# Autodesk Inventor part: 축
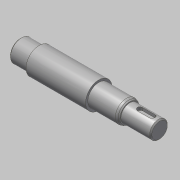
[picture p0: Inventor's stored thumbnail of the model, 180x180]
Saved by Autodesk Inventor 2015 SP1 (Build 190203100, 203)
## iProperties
Created: 2016-06
Part Number: 축
Material: 강철, 연강
Document SubType Name: Modeling
Designer: mduedu
Density: 7.86 g/cm^3
Appearance: 강철
Author: mduedu
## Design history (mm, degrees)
sketch "스케치1"
  geometry: L1 (-63, 0)-(63, 0); L2 (-63, 0)-(-63, 10); L3 (-63, 10)-(-46, 10); L4 (-46, 10)-(-46, 12); L5 (-46, 12)-(8, 12); L6 (8, 12)-(8, 10); L7 (8, 10)-(36, 10); L8 (36, 10)-(36, 8); L9 (36, 8)-(63, 8); L10 (63, 8)-(63, 0); 2 further points
  constraints: 20 end point, 5 parallel, 2 perpendicular, 1 coincident, 1 collinear, 1 horizontal, 1 midpoint, 1 vertical
  dimensions: "d0" = 126 distance of L1.start L1.end; "d2" = 16 diameter of L9 L1; "d3" = 20 diameter of L7 L1; "d4" = 24 diameter of L5 L1; "d5" = 20 diameter of L3 L1; "d6" = 17 distance of L2.end L3.end; "d7" = 27 distance of L8.end L9.end; "d8" = 55 distance from line of L5.end L10
revolve "회전1" sketch "스케치1" stored, may be unused: angle "d9" = 90 deg
chamfer "모따기1" distance "d10" = 2; stored, may be unused: second distance "d11" = 2, angle "d12" = 30 deg
fillet "모깎기1" dims "d13" = 4
node "작업 평면1"
sketch "스케치2"
  geometry: L1 (-4, 2.5)-(7, 2.5); L2 (7, -2.5)-(-4, -2.5); L3 (-4, 0)-(7, 0); L4 (-13.5, 8.845)-(-13.5, -8.845) reference; A1 r 2.5 centre (-4, 0) between (-4, 2.5) and (-4, -2.5); A2 r 2.5 centre (7, 0) between (7, -2.5) and (7, 2.5); 1 further point
  constraints: 6 end point, 4 point on circle, 3 tangent, 2 centre point, 2 parallel, 1 horizontal, 1 horizontal alignment
  dimensions: "d14" = 7 distance edge to line of A1 L4; "d15" = 5 distance between parallel lines of L2 L1; "d16" = 16 dimension on A2 A1
extrude "돌출1" cut sketch "스케치2" distance "d17" = 3; taper "d18" = 0 deg
chamfer "모따기2" distance "d19" = 1; stored, may be unused: second distance "d20" = 2, angle "d21" = 30 deg
sketch "스케치3"
  geometry: L1 (-36, -8)-(-62, -8) reference; L2 (-63, -7)-(-63, 7) reference; L3 (-39.5, -8)-(-41, -6.5); L4 (-41, -6.5)-(-41, -8); L5 (-39.5, -8)-(-41, -8); 1 further point
  constraints: 6 end point, 2 point on line, 1 collinear, 1 vertical
  dimensions: "d22" = 45 deg angle of L4 L3; "d23" = 22 distance between parallel lines of L2 L4; "d24" = 3 diameter of L3.start L4
revolve "회전2" stored, may be unused: angle "d25" = 90 deg
node "작업점1"
sketch "스케치4"
  geometry: 1 further point
hole "구멍1" sketch "스케치4" at (0, 0) diameter "d26" = 3.242; stored, may be unused: countersink angle "d30" = 90 deg, drill point angle "d32" = 120 deg; dims "d27" = 8, "d28" = 4, "d29" = 2, "d31" = 11
chamfer "모따기3" distance "d33" = 2; stored, may be unused: second distance "d34" = 2, angle "d35" = 30 deg
node "솔리드1"
